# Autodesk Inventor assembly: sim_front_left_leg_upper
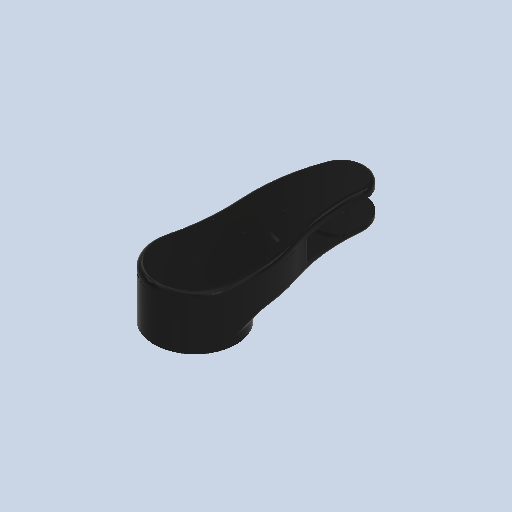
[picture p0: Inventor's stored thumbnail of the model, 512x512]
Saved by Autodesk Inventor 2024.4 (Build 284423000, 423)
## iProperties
Created: 2026-01
Part Number: sim_front_left_leg_upper
Document SubType Name: Assembly
Designer: AdminForWorker
Title: front_left_leg_upper v2
Author: AdminForWorker
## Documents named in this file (3)
- c:\worker\convert-fusion-r06-cosv3\tmp\job-1\16\temp\files\17ab4ec0-f405-4f6b-8c92-517feab2bfe2\2a0df323-7794-401d-9b5e-7b43b5ef5946.iam
- c:\worker\convert-fusion-r06-cosv3\tmp\job-1\16\temp\files\17ab4ec0-f405-4f6b-8c92-517feab2bfe2\leg_upper_inner.ipt
- c:\worker\convert-fusion-r06-cosv3\tmp\job-1\16\temp\files\17ab4ec0-f405-4f6b-8c92-517feab2bfe2\leg_upper_outer.ipt
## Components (2 placed, 2 different names)
1. leg_upper_inner:1
2. leg_upper_outer:1
